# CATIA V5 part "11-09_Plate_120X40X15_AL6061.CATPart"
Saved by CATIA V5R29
Part number: 11-09_Plate_120X40X15_AL6061_Cover
Bounding box of the stored display mesh (mm): x -60 to 60, y -20 to 20, z 0 to 15
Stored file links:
  C:\Users\Administrator\Desktop\프로젝트\Boxfold\Foot\11-09_Plate_120X40X15_AL6061.CATPart
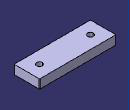
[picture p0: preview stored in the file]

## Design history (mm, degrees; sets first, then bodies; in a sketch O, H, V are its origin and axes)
Body1 (main body)
  Sketch1 on xy-plane, origin (0, 0, 0), H (1, 0, 0), V (0, 1, 0)
    line L1 (60, 20) -> (60, -20)
    line L2 (60, -20) -> (-60, -20)
    line L3 (-60, -20) -> (-60, 20)
    line L4 (-60, 20) -> (60, 20)
    length L1 = 40
    length L4 = 120
    vertical: L1 V, L3 V
    horizontal: L2 H, L4 H
    equidistance: L1 L3 O, L2 L4 O
  Pad1: profile Sketch1, direction (0, 0, 1), length 15
  Sketch2 on start face of Pad1, origin (-39.1075, 0.7725, 0), H (1, 0, 0), V (0, -1, 0)
    point P1 (-0.8925, 0.7725)
    reference projected line E1 (-20.8925, 20.7725) -> (99.1075, 20.7725) from edge [start face of Pad1 | face of Pad1 from Sketch1.L2]
    reference projected line E2 (-20.8925, -19.2275) -> (-20.8925, 20.7725) from edge [start face of Pad1 | face of Pad1 from Sketch1.L3]
    distance P1 E1 = 20
    distance P1 E2 = 20
  Hole1: placed by Sketch2, at (-40, 0, 0) direction (0, 0, 1), diameter 9, through (limit type 3), counterbore diameter 14, counterbore depth 8.6
  Mirror1: of Hole1, about yz-plane
  Fillet1: radius 1, on edge [face of Pad1 from Sketch1.L3 | face of Pad1 from Sketch1.L4]; edge [start face of Pad1 | face of Pad1 from Sketch1.L3]; edge [start face of Pad1 | face of Pad1 from Sketch1.L4]; edge [face of Pad1 from Sketch1.L4 | face of Pad1 from Sketch1.L1]; edge [start face of Pad1 | face of Pad1 from Sketch1.L1]; edge [face of Pad1 from Sketch1.L1 | face of Pad1 from Sketch1.L2]; edge [start face of Pad1 | face of Pad1 from Sketch1.L2]; edge [face of Pad1 from Sketch1.L2 | face of Pad1 from Sketch1.L3]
